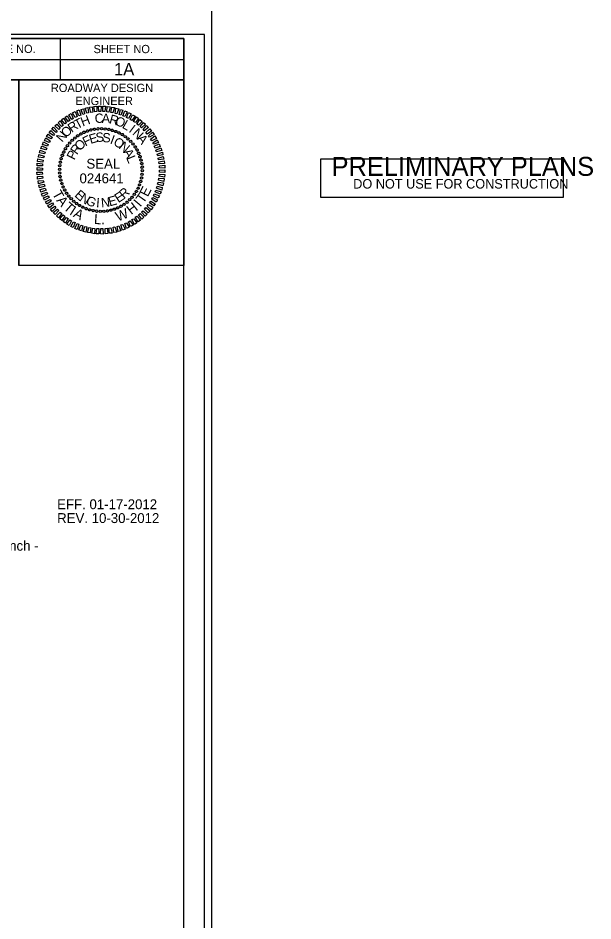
# Model space of a CAD drawing. Extents: x 2241278 to 2254132, y 649924 to 670434.
# Drawn here: x 2252389 to 2254132, y 652610 to 655349 of the extents above; entities that cross this region are included whole.
import ezdxf

# ---------------------------------------------------------------- set-up
doc = ezdxf.new("R2010")
doc.units = 0
for name, color, linetype in [('Sheet Data Field CELL', 7, 'Continuous'), ('Sheet Data Text CELL', 7, 'Continuous'), ('Sheet Plan CELL', 7, 'Continuous'), ('Sheet Plot Border Inside CELL', 7, 'Continuous'), ('Sheet Plot Border Outside CELL', 7, 'Continuous'), ('Sheet Professional Seal CELL', 7, 'Continuous'), ('Sheet Sticker Preliminary CELL', 7, 'Continuous')]:
    doc.layers.add(name, color=color, linetype=linetype)

msp = doc.modelspace()

# ---------------------------------------------------------------- linework, layer by layer
at = {"layer": 'Sheet Plan CELL'}
for p, q in [((2252516.3, 655286.4), (2252516.3, 655161.4)), ((2251891, 655223.9), (2252891.3, 655223.9)), ((2251891, 655161.4), (2252891.3, 655161.4)), ((2251891, 655161.4), (2252891.3, 655161.4)), ((2252391.3, 655161.4), (2252391.3, 654599.2))]:
    msp.add_line(p, q, dxfattribs=at)
for points in [[(2252891.3, 655286.7), (2245391.3, 655286.7), (2245391.3, 650036.7), (2252891.3, 650036.7)], [(2251891, 655286.7), (2252891.3, 655286.7), (2252891.3, 655161.4), (2251891, 655161.4)], [(2252391.3, 655161.4), (2252891.3, 655161.4), (2252891.3, 654598.9), (2252391.3, 654598.9)]]:
    msp.add_lwpolyline(points, close=True, dxfattribs=at)
at = {"layer": 'Sheet Plot Border Inside CELL'}
msp.add_lwpolyline([(2244623.8, 650024.2), (2252953.8, 650024.2), (2252953.8, 655299.2), (2244623.8, 655299.2)], close=True, dxfattribs=at)
at = {"layer": 'Sheet Plot Border Outside CELL'}
msp.add_lwpolyline([(2244558.8, 649924.2), (2252976.3, 649924.2), (2252976.3, 655399.2), (2244558.8, 655399.2)], close=True, dxfattribs=at)
at = {"layer": 'Sheet Professional Seal CELL'}
for p, q in [((2252589.1, 655002.7), (2252589.1, 655002.7)), ((2252599.1, 655006.7), (2252599.1, 655006.7)), ((2252609.5, 655009.7), (2252609.5, 655009.7)), ((2252620.5, 655011.7), (2252620.5, 655011.7)), ((2252631.3, 655013.2), (2252631.3, 655013.2)), ((2252642.3, 655013.5), (2252642.3, 655013.5)), ((2252653.3, 655012.7), (2252653.3, 655012.7)), ((2252664, 655011), (2252664, 655011)), ((2252674.6, 655008.7), (2252674.6, 655008.7)), ((2252685.1, 655005.2), (2252685.1, 655005.2)), ((2252552.8, 654978.2), (2252552.8, 654978.2)), ((2252561.1, 654985.7), (2252561.1, 654985.7)), ((2252569.8, 654992), (2252569.8, 654992)), ((2252579.3, 654997.7), (2252579.3, 654997.7)), ((2252695.1, 655000.7), (2252695.1, 655000.7)), ((2252704.8, 654995.7), (2252704.8, 654995.7)), ((2252713.8, 654989.5), (2252713.8, 654989.5)), ((2252722.6, 654982.7), (2252722.6, 654982.7)), ((2252730.3, 654975.3), (2252730.3, 654975.3)), ((2252532.3, 654952.7), (2252532.3, 654952.7)), ((2252538.6, 654961.7), (2252538.6, 654961.7)), ((2252545.3, 654970.5), (2252545.3, 654970.5)), ((2252737.8, 654967), (2252737.8, 654967)), ((2252744.1, 654958.3), (2252744.1, 654958.3)), ((2252749.8, 654948.8), (2252749.8, 654948.8)), ((2252519.3, 654922.4), (2252519.3, 654922.4)), ((2252522.8, 654933), (2252522.8, 654933)), ((2252527.3, 654943), (2252527.3, 654943)), ((2252754.8, 654939), (2252754.8, 654939)), ((2252758.8, 654929), (2252758.8, 654929)), ((2252515.3, 654901.2), (2252515.3, 654901.2)), ((2252517.1, 654911.9), (2252517.1, 654911.9)), ((2252761.8, 654918.5), (2252761.8, 654918.5)), ((2252763.8, 654907.5), (2252763.8, 654907.5)), ((2252765.3, 654896.8), (2252765.3, 654896.8)), ((2252514.6, 654890.2), (2252514.6, 654890.2)), ((2252514.8, 654879.2), (2252514.8, 654879.2)), ((2252516.3, 654868.4), (2252516.3, 654868.4)), ((2252640.1, 654888), (2252640.1, 654888)), ((2252764.8, 654874.8), (2252764.8, 654874.8)), ((2252765.6, 654885.8), (2252765.6, 654885.8)), ((2252518.3, 654857.4), (2252518.3, 654857.4)), ((2252521.3, 654846.9), (2252521.3, 654846.9)), ((2252525.3, 654837), (2252525.3, 654837)), ((2252757.3, 654843), (2252757.3, 654843)), ((2252760.8, 654853.5), (2252760.8, 654853.5)), ((2252763.1, 654864), (2252763.1, 654864)), ((2252530.3, 654827.2), (2252530.3, 654827.2)), ((2252536.1, 654817.7), (2252536.1, 654817.7)), ((2252741.6, 654814.3), (2252741.6, 654814.3)), ((2252747.8, 654823.3), (2252747.8, 654823.3)), ((2252752.8, 654833), (2252752.8, 654833)), ((2252542.3, 654809), (2252542.3, 654809)), ((2252549.9, 654800.7), (2252549.9, 654800.7)), ((2252557.6, 654793.2), (2252557.6, 654793.2)), ((2252566.4, 654786.5), (2252566.4, 654786.5)), ((2252710.4, 654784), (2252710.4, 654784)), ((2252719.1, 654790.2), (2252719.1, 654790.2)), ((2252727.4, 654797.8), (2252727.4, 654797.8)), ((2252734.9, 654805.5), (2252734.9, 654805.5)), ((2252575.4, 654780.2), (2252575.4, 654780.2)), ((2252585.1, 654775.2), (2252585.1, 654775.2)), ((2252595.1, 654770.7), (2252595.1, 654770.7)), ((2252605.6, 654767.2), (2252605.6, 654767.2)), ((2252616.1, 654765), (2252616.1, 654765)), ((2252626.9, 654763.2), (2252626.9, 654763.2)), ((2252637.9, 654762.5), (2252637.9, 654762.5)), ((2252648.9, 654762.7), (2252648.9, 654762.7)), ((2252659.6, 654764.2), (2252659.6, 654764.2)), ((2252670.6, 654766.2), (2252670.6, 654766.2)), ((2252681.1, 654769.2), (2252681.1, 654769.2)), ((2252691.1, 654773.2), (2252691.1, 654773.2)), ((2252700.9, 654778.2), (2252700.9, 654778.2))]:
    msp.add_line(p, q, dxfattribs=at)
for points in [[(2252551.5, 655041.7), (2252542.3, 655055.2), (2252550, 655059.2), (2252556.3, 655044.7)], [(2252562.3, 655047.7), (2252554.3, 655061.7), (2252562, 655065.2), (2252567.8, 655050)], [(2252573.3, 655053), (2252566.8, 655067.5), (2252574.3, 655070.5), (2252579.5, 655054.5)], [(2252585.5, 655057), (2252579.8, 655072), (2252587.5, 655074.2), (2252590.8, 655058.7)], [(2252597.5, 655060.2), (2252592.3, 655076), (2252600.8, 655077.7), (2252602.8, 655061.5)], [(2252609.5, 655063), (2252605.5, 655079), (2252613.8, 655079.7), (2252615.5, 655063.7)], [(2252621.5, 655064.5), (2252618.8, 655080.5), (2252627.3, 655081.5), (2252627.5, 655065.2)], [(2252634, 655065.7), (2252632.8, 655082), (2252641, 655081.7), (2252640, 655065.5)], [(2252646, 655065.5), (2252646, 655081.7), (2252654.3, 655081.5), (2252652, 655065.2)], [(2252658.5, 655064.7), (2252659.5, 655081), (2252667.8, 655079.5), (2252664.5, 655063.7)], [(2252670.5, 655062.7), (2252672.8, 655078.7), (2252681, 655077.5), (2252676.5, 655062)], [(2252683.3, 655060), (2252685.8, 655076.2), (2252694.3, 655074.2), (2252688.5, 655058.7)], [(2252695.3, 655056.7), (2252699, 655072.2), (2252706.8, 655069.7), (2252700.5, 655055)], [(2252706.5, 655052.2), (2252712.3, 655068), (2252719.3, 655065), (2252712.3, 655050.5)], [(2252717.8, 655047.5), (2252724, 655062.3), (2252731.8, 655058.8), (2252723.3, 655044.8)], [(2252729.3, 655041.8), (2252736, 655056), (2252743.5, 655051.8), (2252734, 655038.8)], [(2252521, 655020.2), (2252510, 655031.2), (2252516, 655037.2), (2252525.8, 655023.7)], [(2252531, 655028), (2252520.3, 655039.9), (2252527, 655045.2), (2252535.8, 655031.2)], [(2252540.5, 655035.5), (2252531.3, 655048.2), (2252537.8, 655053), (2252546, 655038.5)], [(2252739, 655035), (2252747.8, 655049.5), (2252754.3, 655044.3), (2252744.5, 655032)], [(2252749.3, 655027.5), (2252758.5, 655041.3), (2252765, 655035.8), (2252754, 655024)], [(2252758.8, 655019.8), (2252769, 655032.8), (2252775, 655026.8), (2252763.5, 655016)], [(2252496.6, 654992.4), (2252483.1, 655000.9), (2252487.8, 655008.2), (2252499.8, 654997.2)], [(2252504.1, 655001.9), (2252491, 655011.7), (2252496.5, 655018.2), (2252507.6, 655006.4)], [(2252512.8, 655011.4), (2252500, 655021.7), (2252506.3, 655027.4), (2252516.8, 655015.4)], [(2252767.8, 655011), (2252778.5, 655022.8), (2252784.5, 655016.8), (2252771.6, 655007)], [(2252776.6, 655002), (2252788, 655013.3), (2252793.3, 655006.5), (2252780.1, 654997)], [(2252784.1, 654992.3), (2252796.3, 655002.8), (2252801.1, 654995.5), (2252787.1, 654987.5)], [(2252483.1, 654971.7), (2252468.8, 654977.9), (2252472.6, 654985.7), (2252486.1, 654976.4)], [(2252489.1, 654982.4), (2252475.1, 654989.9), (2252480.1, 654996.9), (2252493.1, 654986.9)], [(2252790.6, 654982), (2252803.8, 654991.5), (2252808.6, 654984), (2252794.1, 654977)], [(2252797.1, 654971), (2252811.1, 654979.8), (2252814.3, 654972), (2252800.1, 654966.3)], [(2252469.3, 654937.2), (2252453.8, 654940.4), (2252455.6, 654948.7), (2252471.3, 654942.4)], [(2252473.1, 654949.2), (2252457.6, 654953.7), (2252460.8, 654961.4), (2252475.8, 654954.4)], [(2252478.1, 654960.2), (2252462.6, 654965.9), (2252466.3, 654973.7), (2252480.6, 654965.7)], [(2252802.1, 654960.3), (2252816.8, 654967.8), (2252820.1, 654959.8), (2252804.6, 654954.8)], [(2252806.6, 654948.5), (2252821.8, 654955), (2252824.6, 654947.3), (2252809.1, 654943.3)], [(2252464.1, 654912.4), (2252448.1, 654913.9), (2252449.1, 654922.4), (2252465.3, 654918.4)], [(2252466.1, 654925.2), (2252450.6, 654927.2), (2252452.3, 654935.7), (2252468.1, 654930.4)], [(2252810.6, 654936.5), (2252826.6, 654942.3), (2252828.1, 654934), (2252812.3, 654931.3)], [(2252813.6, 654924.5), (2252829.3, 654929.3), (2252830.8, 654920.8), (2252815.1, 654919.3)], [(2252462.6, 654887.9), (2252446.3, 654887.2), (2252446.3, 654895.7), (2252462.6, 654893.9)], [(2252462.8, 654900.4), (2252446.6, 654900.9), (2252447.1, 654909.2), (2252463.3, 654906.4)], [(2252815.8, 654912.5), (2252832.1, 654916), (2252832.8, 654907.5), (2252816.8, 654906.5)], [(2252817.3, 654900.5), (2252833.6, 654902.5), (2252834.1, 654894), (2252817.8, 654894.5)], [(2252462.8, 654875.4), (2252446.6, 654873.4), (2252446.1, 654881.9), (2252462.3, 654881.4)], [(2252464.3, 654863.4), (2252448.1, 654859.9), (2252447.3, 654868.4), (2252463.3, 654869.4)], [(2252817.3, 654875.5), (2252833.6, 654875), (2252833.1, 654866.8), (2252816.8, 654869.5)], [(2252817.6, 654888), (2252833.8, 654888.8), (2252833.8, 654880.3), (2252817.6, 654882)], [(2252466.6, 654851.4), (2252450.8, 654846.7), (2252449.3, 654855.2), (2252465.1, 654856.7)], [(2252469.6, 654839.4), (2252453.6, 654833.7), (2252452.1, 654841.9), (2252467.8, 654844.7)], [(2252810.8, 654838.8), (2252826.3, 654835.5), (2252824.6, 654827.3), (2252808.8, 654833.5)], [(2252814.1, 654850.8), (2252829.6, 654848.8), (2252827.8, 654840.3), (2252812.1, 654845.5)], [(2252816.1, 654863.5), (2252832.1, 654862), (2252831.1, 654853.5), (2252814.8, 654857.5)], [(2252473.6, 654827.4), (2252458.3, 654820.9), (2252455.6, 654828.7), (2252471.1, 654832.7)], [(2252478.1, 654815.7), (2252463.4, 654808.2), (2252460.1, 654816.2), (2252475.6, 654821.2)], [(2252483.1, 654804.9), (2252469.1, 654796.2), (2252465.9, 654803.9), (2252480.1, 654809.7)], [(2252802.1, 654815.8), (2252817.6, 654810), (2252813.9, 654802.3), (2252799.6, 654810.3)], [(2252807.1, 654826.8), (2252822.6, 654822.3), (2252819.3, 654814.5), (2252804.3, 654821.5)], [(2252489.6, 654793.9), (2252476.4, 654784.4), (2252471.6, 654791.9), (2252486.1, 654798.9)], [(2252496.1, 654783.7), (2252483.9, 654773.2), (2252479.1, 654780.4), (2252493.1, 654788.4)], [(2252783.6, 654783.5), (2252797.1, 654775), (2252792.4, 654767.8), (2252780.4, 654778.8)], [(2252791.1, 654793.5), (2252805.1, 654786), (2252800.1, 654779), (2252787.1, 654789)], [(2252797.1, 654804.3), (2252811.4, 654798), (2252807.6, 654790.3), (2252794.1, 654799.5)], [(2252503.6, 654773.9), (2252492.1, 654762.7), (2252486.9, 654769.4), (2252500.1, 654778.9)], [(2252512.4, 654764.9), (2252501.6, 654753.2), (2252495.6, 654759.2), (2252508.6, 654768.9)], [(2252521.4, 654756.2), (2252511.1, 654743.2), (2252505.1, 654749.2), (2252516.6, 654759.9)], [(2252759.1, 654755.8), (2252770.1, 654744.8), (2252764.1, 654738.8), (2252754.4, 654752.3)], [(2252767.4, 654764.5), (2252780.1, 654754.3), (2252773.9, 654748.5), (2252763.4, 654760.5)], [(2252776.1, 654774), (2252789.1, 654764.3), (2252783.6, 654757.8), (2252772.6, 654769.5)], [(2252530.9, 654748.5), (2252521.6, 654734.7), (2252515.1, 654740.2), (2252526.1, 654752)], [(2252541.1, 654741), (2252532.4, 654726.5), (2252525.9, 654731.7), (2252535.6, 654744)], [(2252550.9, 654734.2), (2252544.1, 654720), (2252536.6, 654724.2), (2252546.1, 654737.2)], [(2252562.4, 654728.5), (2252556.1, 654713.7), (2252548.4, 654717.2), (2252556.9, 654731.2)], [(2252717.9, 654728.2), (2252725.9, 654714.3), (2252718.1, 654710.7), (2252712.4, 654726)], [(2252728.6, 654734.3), (2252737.9, 654720.8), (2252730.1, 654716.8), (2252723.9, 654731.3)], [(2252739.6, 654740.5), (2252748.9, 654727.8), (2252742.4, 654723), (2252734.1, 654737.5)], [(2252749.1, 654748), (2252759.9, 654736), (2252753.1, 654730.8), (2252744.4, 654744.8)], [(2252573.6, 654723.7), (2252567.9, 654708), (2252560.9, 654711), (2252567.9, 654725.5)], [(2252584.9, 654719.2), (2252581.1, 654703.7), (2252573.4, 654706.2), (2252579.6, 654721)], [(2252596.9, 654716), (2252594.4, 654699.7), (2252585.9, 654701.7), (2252591.6, 654717.2)], [(2252609.6, 654713.2), (2252607.4, 654697.2), (2252599.1, 654698.5), (2252603.6, 654714)], [(2252621.6, 654711.2), (2252620.6, 654695), (2252612.4, 654696.5), (2252615.6, 654712.2)], [(2252634.1, 654710.5), (2252634.1, 654694.2), (2252625.9, 654694.5), (2252628.1, 654710.7)], [(2252646.1, 654710.2), (2252647.4, 654694), (2252639.1, 654694.2), (2252640.1, 654710.5)], [(2252658.6, 654711.5), (2252661.4, 654695.5), (2252652.9, 654694.5), (2252652.6, 654710.7)], [(2252670.6, 654713), (2252674.6, 654697), (2252666.4, 654696.2), (2252664.6, 654712.2)], [(2252682.6, 654715.7), (2252687.9, 654700), (2252679.4, 654698.2), (2252677.4, 654714.5)], [(2252694.6, 654719), (2252700.4, 654704), (2252692.6, 654701.7), (2252689.4, 654717.2)], [(2252706.9, 654723), (2252713.4, 654708.5), (2252705.9, 654705.5), (2252700.6, 654721.5)]]:
    msp.add_lwpolyline(points, close=True, dxfattribs=at)
for centre, major_axis in [((2252579.3, 654997.6), (-1.75, 3.15)), ((2252589, 655002.5), (-1.47, 3.29)), ((2252599.2, 655006.5), (-1.17, 3.4)), ((2252609.7, 655009.6), (-0.87, 3.49)), ((2252620.4, 655011.8), (-0.56, 3.56)), ((2252631.3, 655013.1), (-0.25, 3.59)), ((2252642.2, 655013.4), (0.06, 3.6)), ((2252653.2, 655012.7), (0.38, 3.58)), ((2252664, 655011.1), (0.69, 3.53)), ((2252674.6, 655008.5), (0.99, 3.46)), ((2252685, 655005.1), (1.29, 3.36)), ((2252695, 655000.7), (1.58, 3.24)), ((2252545.4, 654970.2), (-2.72, 2.36)), ((2252552.9, 654978.2), (-2.5, 2.59)), ((2252561.1, 654985.4), (-2.27, 2.8)), ((2252569.9, 654991.9), (-2.01, 2.98)), ((2252704.6, 654995.5), (1.85, 3.09)), ((2252713.8, 654989.4), (2.12, 2.91)), ((2252722.3, 654982.6), (2.36, 2.72)), ((2252730.3, 654975.1), (2.59, 2.5)), ((2252527.4, 654942.9), (-3.24, 1.58)), ((2252532.6, 654952.5), (-3.09, 1.85)), ((2252538.6, 654961.7), (-2.91, 2.12)), ((2252737.5, 654966.9), (2.8, 2.27)), ((2252744, 654958.1), (2.98, 2.01)), ((2252749.7, 654948.8), (3.15, 1.75)), ((2252519.5, 654922.5), (-3.46, 0.99)), ((2252523, 654932.9), (-3.36, 1.29)), ((2252754.6, 654939), (3.29, 1.47)), ((2252758.6, 654928.8), (3.4, 1.17)), ((2252761.7, 654918.3), (3.49, 0.87)), ((2252514.7, 654890.1), (-3.6, 0.06)), ((2252515.4, 654901.1), (-3.58, 0.38)), ((2252517, 654911.9), (-3.53, 0.69)), ((2252763.9, 654907.6), (3.56, 0.56)), ((2252765.2, 654896.8), (3.59, 0.25)), ((2252515, 654879.2), (-3.59, -0.25)), ((2252516.2, 654868.3), (-3.56, -0.56)), ((2252763.2, 654864.1), (3.53, -0.69)), ((2252764.8, 654874.9), (3.58, -0.38)), ((2252765.5, 654885.8), (3.6, -0.06)), ((2252518.4, 654857.6), (-3.49, -0.87)), ((2252521.5, 654847.1), (-3.4, -1.17)), ((2252525.5, 654836.9), (-3.29, -1.47)), ((2252752.8, 654833), (3.24, -1.58)), ((2252757.2, 654843.1), (3.36, -1.29)), ((2252760.6, 654853.4), (3.46, -0.99)), ((2252530.4, 654827.2), (-3.15, -1.75)), ((2252536.1, 654817.8), (-2.98, -2.01)), ((2252542.6, 654809), (-2.8, -2.27)), ((2252734.7, 654805.7), (2.72, -2.36)), ((2252741.5, 654814.3), (2.91, -2.12)), ((2252747.6, 654823.4), (3.09, -1.85)), ((2252549.9, 654800.8), (-2.59, -2.5)), ((2252557.8, 654793.3), (-2.36, -2.72)), ((2252566.4, 654786.5), (-2.12, -2.91)), ((2252575.5, 654780.5), (-1.85, -3.09)), ((2252700.9, 654778.3), (1.75, -3.15)), ((2252710.2, 654784), (2.01, -2.98)), ((2252719, 654790.5), (2.27, -2.8)), ((2252727.2, 654797.8), (2.5, -2.59)), ((2252585.1, 654775.3), (-1.58, -3.24)), ((2252595.2, 654770.9), (-1.29, -3.36)), ((2252605.5, 654767.4), (-0.99, -3.46)), ((2252616.2, 654764.9), (-0.69, -3.53)), ((2252627, 654763.3), (-0.38, -3.58)), ((2252637.9, 654762.6), (-0.06, -3.6)), ((2252648.9, 654762.9), (0.25, -3.59)), ((2252659.7, 654764.1), (0.56, -3.56)), ((2252670.4, 654766.3), (0.87, -3.49)), ((2252680.9, 654769.4), (1.17, -3.4)), ((2252691.1, 654773.4), (1.47, -3.29))]:
    msp.add_ellipse(centre, major_axis=major_axis, ratio=0.999708, dxfattribs=at)
at = {"layer": 'Sheet Sticker Preliminary CELL'}
msp.add_lwpolyline([(2253307.3, 654804.6), (2253307.3, 654922.1), (2254042.3, 654922.1), (2254042.3, 654804.6)], close=True, dxfattribs=at)

# ---------------------------------------------------------------- texts
at = {"layer": 'Sheet Data Field CELL'}
msp.add_text('1A', height=37.5, dxfattribs=at).set_placement((2252679.9, 655175.4))
at = {"layer": 'Sheet Data Text CELL'}
for s, p in [('EFF. 01-17-2012', (2252507.3, 653859.1)), ('REV. 10-30-2012', (2252507.3, 653817.1)), ('The following Roadway Standards as appear in "Roadway Standard Drawings" Highway Design Branch -', (2250587.3, 653733.1))]:
    msp.add_text(s, height=30, dxfattribs=at).set_placement(p)
at = {"layer": 'Sheet Plan CELL'}
for s, p in [('PROJECT REFERENCE NO.', (2252002, 655243.2)), ('SHEET NO.', (2252617.8, 655242.7)), ('ROADWAY DESIGN', (2252488.3, 655124.9)), ('ENGINEER', (2252562.5, 655085.2))]:
    msp.add_text(s, height=25, dxfattribs=at).set_placement(p)
at = {"layer": 'Sheet Professional Seal CELL'}
for s, height, rotation, p in [('C', 28.2, 6.2342, (2252622.8, 655029.7)), ('A', 28.2, 359.0346, (2252642.5, 655031.2)), ('R', 28.2, 344.6354, (2252663.5, 655030.2)), ('R', 28.2, 35.0348, (2252551.6, 655000.5)), ('T', 28.2, 27.8341, (2252568.5, 655011.5)), ('H', 28.2, 20.6338, (2252584.8, 655019.7)), ('O', 28.2, 337.4355, (2252680.3, 655026.5)), ('L', 28.2, 330.2352, (2252702.3, 655017.2)), ('N', 28.2, 49.4378, (2252522.8, 654970.5)), ('O', 28.2, 42.2361, (2252534.3, 654985)), ('S', 28.2, 7.2699, (2252626.1, 654972.2)), ('I', 28.2, 323.0345, (2252722.6, 655005.2)), ('N', 28.2, 315.8332, (2252733.3, 654997.5)), ('O', 28.2, 44.6956, (2252576.3, 654944.7)), ('F', 28.2, 25.9814, (2252592.8, 654959.5)), ('E', 28.2, 16.6254, (2252608.8, 654967)), ('S', 28.2, 357.9147, (2252644.1, 654972.5)), ('I', 28.2, 339.2039, (2252665.6, 654969)), ('O', 28.2, 329.8478, (2252675.6, 654965.5)), ('N', 28.2, 320.4909, (2252692.3, 654955.5)), ('A', 28.2, 308.6315, (2252748.1, 654982.8)), ('P', 28.2, 63.4132, (2252559.6, 654916.5)), ('R', 28.2, 54.054, (2252567.6, 654932.5)), ('A', 28.2, 301.7746, (2252706.6, 654942.5)), ('SEAL', 29.99, 0.0143, (2252596.1, 654892.2)), ('L', 28.2, 292.4152, (2252716.3, 654925.2)), ('024641', 29.99, 0.0143, (2252575.2, 654847.9)), ('E', 30, 63.1332, (2252782.3, 654804.7)), ('T', 30, 299.1795, (2252491.6, 654816.5)), ('E', 28.2, 318.2912, (2252558.1, 654809.7)), ('N', 28.2, 327.6483, (2252573.1, 654796.2)), ('E', 28.2, 14.4261, (2252666.4, 654777.7)), ('E', 28.2, 33.1384, (2252692.9, 654787.5)), ('R', 28.2, 42.4957, (2252710.6, 654799.2)), ('T', 30, 54.6114, (2252768.4, 654784.6)), ('A', 30, 307.7013, (2252503.8, 654795.3)), ('T', 30, 318.7796, (2252524.2, 654770.9)), ('G', 28.2, 337.0046, (2252592.1, 654785)), ('I', 28.2, 355.7155, (2252624.9, 654775.5)), ('N', 28.2, 5.0707, (2252641.6, 654774.7)), ('H', 30, 37.3353, (2252731.9, 654751.2)), ('I', 30, 49.8469, (2252759.3, 654774.3)), ('I', 30, 327.3015, (2252542.8, 654755)), ('A', 30, 332.0659, (2252554.2, 654747.4)), ('W', 30, 21.6281, (2252691.4, 654731.4)), ('L', 30, 355.927, (2252618.4, 654724.7)), ('.', 30, 3.7904, (2252641, 654723.2))]:
    msp.add_text(s, height=height, rotation=rotation, dxfattribs=at).set_placement(p)
at = {"layer": 'Sheet Sticker Preliminary CELL'}
for s, height, p in [('PRELIMINARY PLANS', 57.6, (2253339.8, 654870.4)), ('DO NOT USE FOR CONSTRUCTION', 28.8, (2253405.3, 654831.9))]:
    msp.add_text(s, height=height, dxfattribs=at).set_placement(p)

doc.saveas('drawing.dxf')
